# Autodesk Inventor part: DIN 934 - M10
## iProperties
Created: 2006-02
Part Number: DIN 934 - M10
Material: Steel, Mild
Description: Hex Nut
Document SubType Name: Modeling
Standard: DIN 934
Designer: Andy Moles
Standards Organization: DIN
Language: en-US
Size Designation: M10
Categories: <MemberInstance><Categories><Category DisplayName="Fasteners" InternalName="e4da775c-781d-43d5-af7c-5136215cf5a6" Mnemonic="FSTN"><Category DisplayName="Nuts" I
Mass: 11.7561 g
Surface Area: 9.86681 cm^2
Volume: 1.49568 cm^3
Density: 7.86 g/cm^3
Author: Andy Moles
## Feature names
1. Body [Extrusion]
2. Chamfer1 [Revolution]
3. Thread [Hole]
4. Chamfer2
5. Chamfer3
